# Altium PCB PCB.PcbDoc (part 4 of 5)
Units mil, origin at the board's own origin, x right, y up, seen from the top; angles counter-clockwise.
Board outline 8070.87 x 4448.94 mil, 4 copper layers (Top Layer, Layer 1, Layer 2, Bottom Layer), stack 23.756 mil thick; 263 components, 330 nets, 1677 pads, 1186 vias.
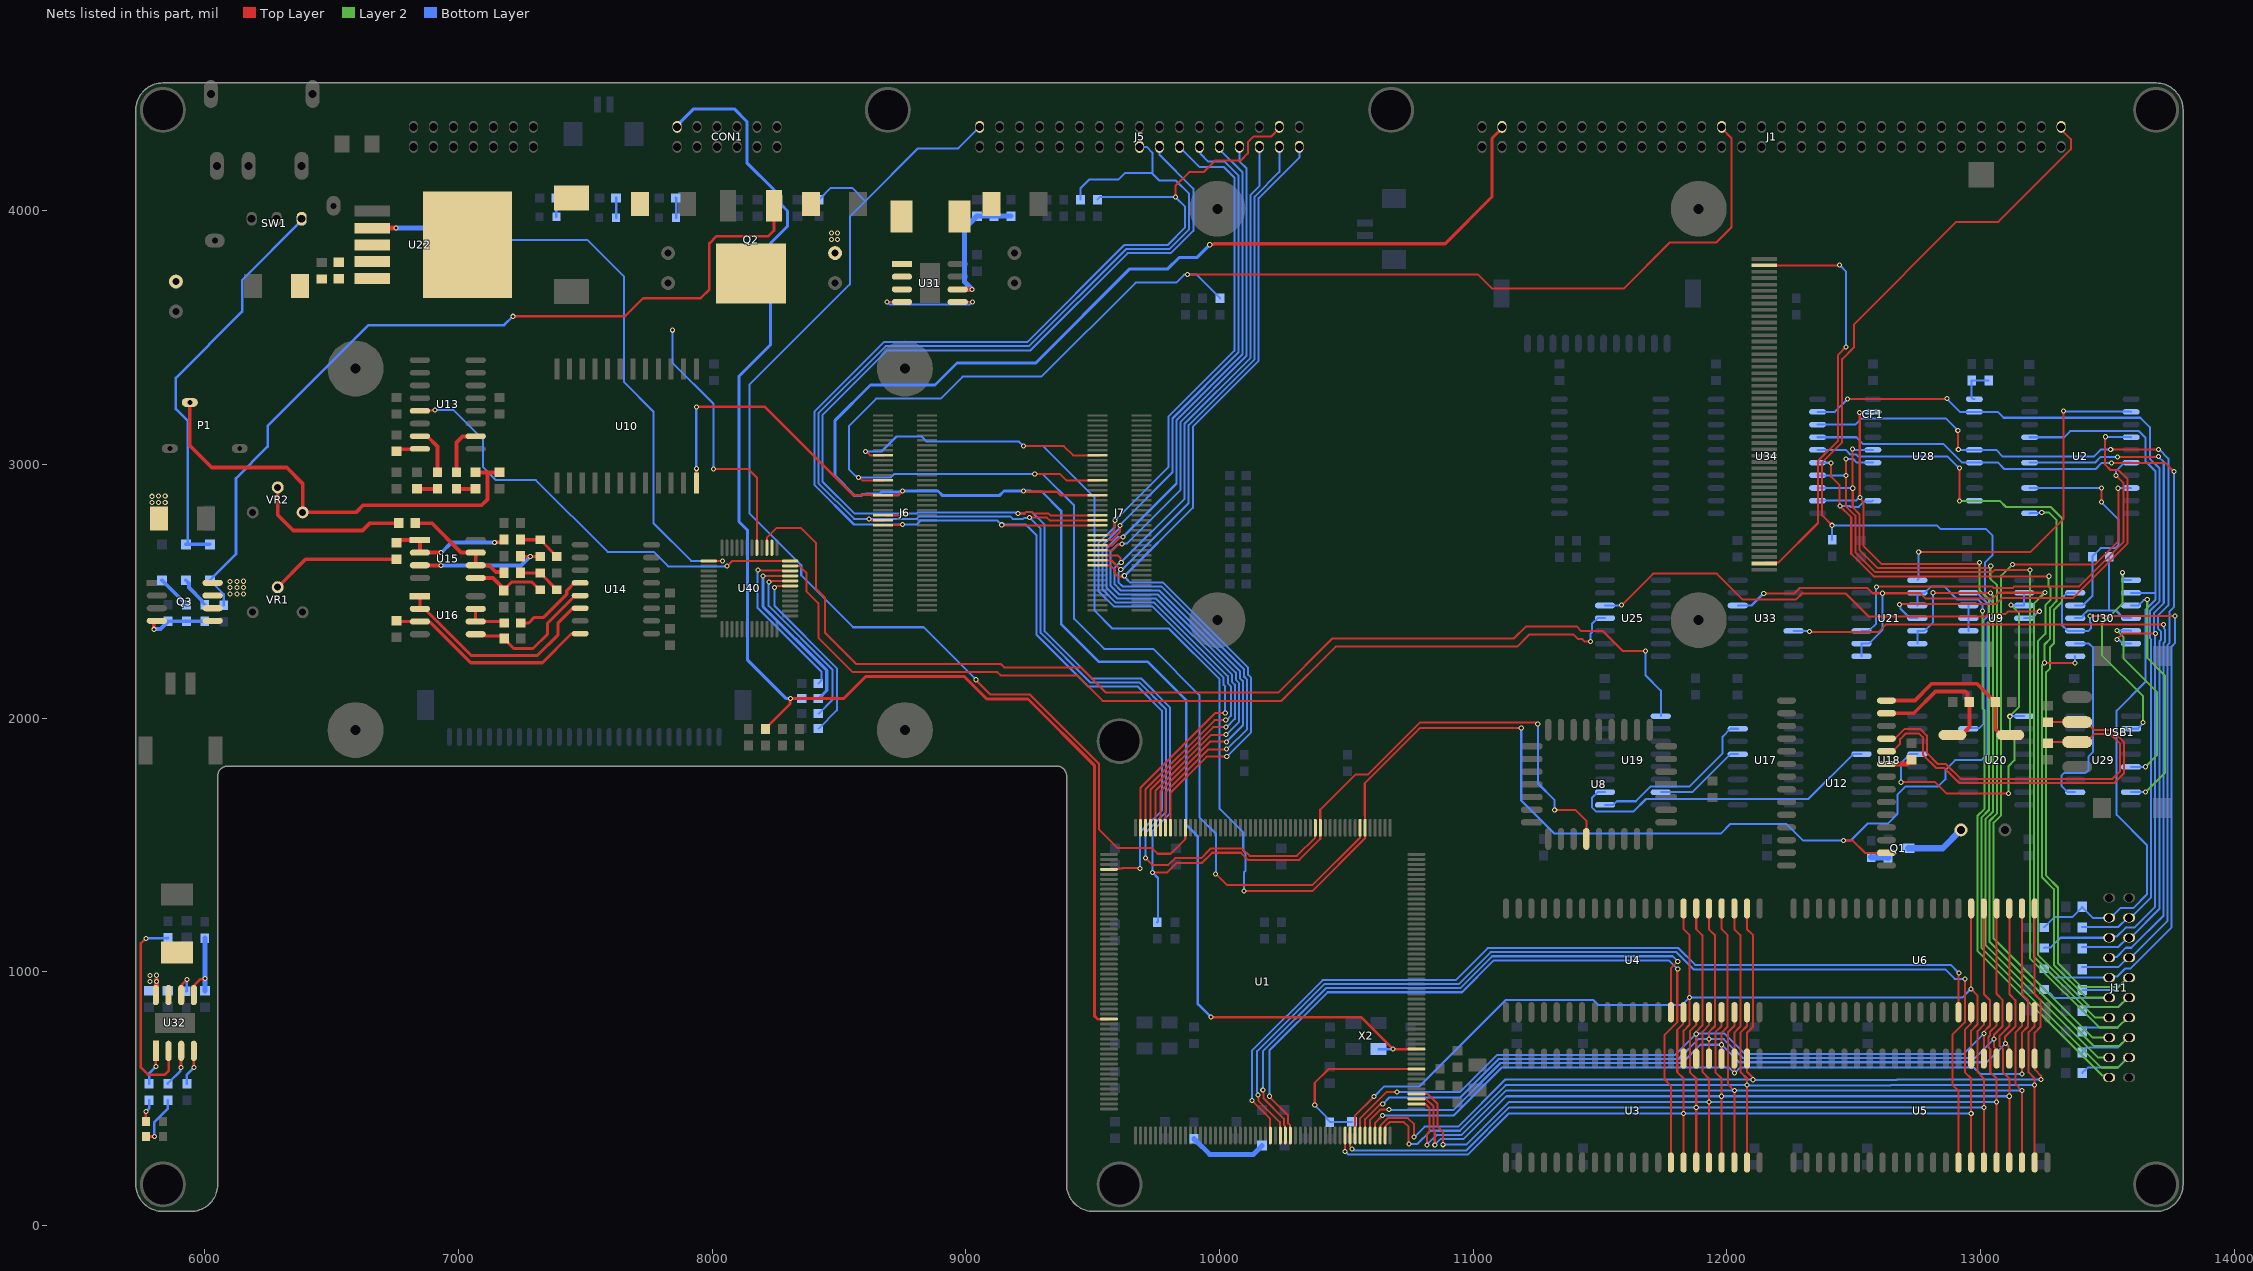
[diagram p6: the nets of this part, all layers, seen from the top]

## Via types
v1: diameter 20, hole 12, Top Layer to Bottom Layer, tented both sides, 1165 vias
v2: diameter 19.68, hole 11.81, Top Layer to Bottom Layer, tented both sides, 10 vias
v3: diameter 27.56, hole 27.56, Top Layer to Bottom Layer, 4 vias
v4: diameter 35.43, hole 35.43, Top Layer to Bottom Layer, 2 vias
v5: diameter 55.12, hole 55.12, Top Layer to Bottom Layer, 2 vias
v6: diameter 66.93, hole 66.93, Top Layer to Bottom Layer, 2 vias
v7: diameter 78.74, hole 78.74, Top Layer to Bottom Layer, 1 vias

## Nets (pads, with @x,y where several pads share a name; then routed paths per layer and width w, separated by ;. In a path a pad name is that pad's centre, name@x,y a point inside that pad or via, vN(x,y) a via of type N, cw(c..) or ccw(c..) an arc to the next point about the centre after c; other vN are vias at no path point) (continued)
LA17: J5.21 J7.32 U1.207 | length 3616.9
  Top Layer w8: J7.32@9527.56,2720.47 9528.48,2721.39 9570.06,2721.39 9586,2737.34 9586,2776.58 v1(9587.7,2778.28) ; U1.207@9688.98,1567.56 9688.98,1725.72 9983.25,2020 v1(10023,2020)
  Bottom Layer w8: J5.21@9842.52,4251.97 9922.49,4172 10018,4172 10059,4131 10059,3447.76 9799,3187.76 9799,3141 9799,2989.59 v1(9587.7,2778.28) 9586.37,2776.96 9586.37,2752 9523,2688.63 9523,2500.86 9584.86,2439 9736.88,2439 10017,2158.88 10017,2130.56 10023,2124.56 v1(10023,2020)
LA18: J5.23 J7.30 U1.206 | length 3592.4
  Top Layer w8: J7.30@9527.56,2700.79 9528.48,2701.71 9574.45,2701.71 9608.37,2735.63 v1(9608.37,2759) ; U1.206@9708.66,1567.56 9708.66,1719.66 9981,1992 v1(10025,1992)
  Bottom Layer w8: J5.23@9921.26,4251.97 9925.61,4247.62 9925.61,4224.39 9956,4194 10020.63,4194 10075,4139.63 10075,3441.14 9815,3181.14 9815,2968.87 9608.37,2762.25 v1(9608.37,2759) 9608,2759 9606.08,2757.08 9606.08,2749.08 9539,2682 9539,2507.49 9591.49,2455 9743.51,2455 10033,2165.51 10033,2137.19 10045,2125.19 10045,2008.77 10028.23,1992 v1(10025,1992)
LA19: J5.25 J7.28 U1.205 | length 3529.8
  Top Layer w8: J7.28@9527.56,2681.1 9576.48,2681.1 9607.02,2711.65 9617.76,2711.65 v1(9620.06,2713.94) ; U1.205@9728.35,1567.56 9728.35,1716.72 9975.63,1964 v1(10026,1964)
  Bottom Layer w8: J5.25@10000,4251.97 10000,4243 10091,4152 10091,3434.51 9831,3174.51 9831,2924.89 v1(9620.06,2713.94) 9619.17,2713.06 9598.06,2713.06 9555,2670 9555,2514.12 9598.12,2471 9750.14,2471 10049,2172.14 10049,2143.82 10061,2131.82 10061,1996.89 10028.11,1964 v1(10026,1964)
LA20: J5.27 J7.26 U1.204 | length 3502.9
  Top Layer w8: J7.26@9527.56,2661.42 9579.42,2661.42 9601.94,2683.94 9613.93,2683.94 v1(9615.96,2685.98) ; U1.204@9748.03,1567.56 9748.03,1713.78 9968.25,1934 10024.69,1934 v1(10025.4,1934.72)
  Bottom Layer w8: v1(9615.96,2685.98) 9613.67,2683.68 9597.68,2683.68 9571,2657 9571,2520.75 9604.75,2487 9756.76,2487 10065,2178.76 10065,2150.44 10077,2138.44 10077,1983.89 10027.83,1934.72 v1(10025.4,1934.72) ; v1@9618.3,2687.3 9634.92,2687.3 9847,2899.37 9847,3167.88 10107,3427.88 10107,4167 10078.74,4195.26 J5.27@10078.74,4251.97
LA21: J5.29 J7.24 U1.203 | length 3501.7
  Top Layer w8: J7.24@9527.56,2641.73 9599.27,2641.73 9610.7,2630.3 9610.7,2616.3 v1(9613,2614) ; U1.203@9767.72,1567.56 9767.72,1710.83 9964.88,1908 10026.2,1908 v1(10028,1906.2)
  Bottom Layer w8: v1(10028,1906.2) 10093,1971.2 10093,2145.07 10081,2157.07 10081,2185.39 9763.39,2503 9611.37,2503 9587,2527.37 9587,2593.02 9601.93,2607.95 9603.71,2607.95 9609.75,2614 v1(9613,2614) 9613,2615.11 9863,2865.11 9863,3161.25 10123,3421.25 10123,4062.63 10157.48,4097.11 J5.29@10157.48,4251.97
LA22: J5.31 J7.22 U1.202 | length 3520.6
  Top Layer w8: J7.22@9527.56,2622.05 9528.48,2621.13 9574.76,2621.13 9609.93,2585.95 v1(9611.05,2585.95) ; U1.202@9787.4,1567.56 9787.4,1707.89 9955.51,1876 10025.79,1876 v1(10027.99,1878.2)
  Bottom Layer w8: v1(9611.05,2585.95) 9611.05,2582.71 9603,2574.66 9603,2534 9618,2519 9770.02,2519 10097,2192.02 10097,2163.7 10109,2151.7 10109,1956.09 10031.11,1878.2 v1(10027.99,1878.2) ; v1@9614.76,2583.76 9879,2848 9879,3154.63 10139,3414.63 10139,4056 10236.22,4153.22 J5.31@10236.22,4251.97
LA23: J5.33 J7.20 U1.201 | length 3559
  Top Layer w8: J7.20@9527.56,2602.36 9528.48,2601.44 9570.06,2601.44 9587.47,2584.03 9587.47,2570.53 9599.3,2558.7 9622.7,2558.7 v1(9625,2561) ; U1.201@9807.09,1567.56 9807.09,1704.95 9950.16,1848.02 v1(10028.92,1848.02)
  Bottom Layer w8: v1@9624,2558 9895,2829 9895,3148 10155,3408 10155,4049.37 10314.96,4209.33 J5.33@10314.96,4251.97 ; v1(9625,2561) 9625,2557.75 9635.6,2547.15 9635.6,2546.15 9646.75,2535 9776.65,2535 10113,2198.65 10113,2170.33 10125,2158.33 10125,1944.1 v1(10028.92,1848.02)
LTP_ACK#: J11.13 U21.8 U21.9 U33.12 | length 3417
  Top Layer w8: v1(12146,2491) 12267,2491 12289,2513 12554,2513 12575,2492 v1(12615,2492) 12763,2492 12784,2471 13049.11,2471 13072.11,2494 13254,2494 v1(13255,2495)
  Layer 2 w8: v1(13255,2495) 13211,2451 13211,1060.12 13452.22,818.9 J11.13@13507.87,818.9
  Bottom Layer w8: U33.12@12043.78,2443.7 12097.7,2443.7 12145,2491 v1(12146,2491) ; U21.8@12531.5,2243.7 U21.9@12531.5,2293.7 12560.5,2293.7 12615,2348.2 v1(12615,2492)
LTP_ATUOFD#: J11.5 R102.1 U2.15 U30.6 | length 3049.6
  Top Layer w8: v1(13538,2310) 13561,2333 v1(13690,2333) ; v1(13540.16,3028.54) 13696.29,3028.54 13698.75,3031 v1(13702,3031)
  Bottom Layer w8: U2.15@13194.49,3007.09 13452.09,3007.09 13474.94,3029.94 13538.76,3029.94 v1(13540.16,3028.54) ; R102.1@13251.97,1093.27 13254.98,1096.28 13278.28,1096.28 13315.86,1133.86 J11.5@13507.87,1133.86 13512.69,1138.67 13537.67,1138.67 13572.55,1173.55 13606.55,1173.55 13689,1256 v1@13689,2333 ; v1(13538,2310) 13540.3,2307.7 13547.22,2307.7 13561.23,2293.7 U30.6@13594.02,2293.7 ; v1(13690,2333) 13690,2336.25 13684,2342.25 13684,2414 13723,2453 13723,3010 v1(13702,3031)
LTP_BUSY: J11.15 U2.8 | length 2839.7
  Top Layer w8: v1(13126,2605) 13451.75,2605 13544,2697.25 13544,2905 v1(13543,2906)
  Layer 2 w8: v1(13126,2605) 13082,2561 13082,1617.49 13052,1587.49 13052,1131 13442.84,740.16 J11.15@13507.87,740.16
  Bottom Layer w8: v1(13543,2906) 13543.55,2906.55 13593.94,2906.55 U2.8@13594.49,2907.09
LTP_D0: C115.1 J11.4 U28.2 U34.2 | length 3585.9
  Top Layer w8: v1(12477,3258) 12477.5,3258.5 12867.5,3258.5 v1(12868,3259)
  Bottom Layer w8: U34.2@12358.27,3207.09 12426.09,3207.09 v1(12477,3258) ; v1@12867.5,3258.5 12918.91,3207.09 U28.2@12976.38,3207.09 13068.91,3207.09 13092,3184 13631,3184 13668,3147 13668,3023 13707,2984 13707,2461 13668,2422 13668,2315 13673,2310 13673,1474 13673,1293.08 13592.52,1212.6 J11.4@13586.61,1212.6 13580.71,1212.6 13544.78,1176.67 C115.1@13401.57,1176.67
LTP_D1: C114.1 J11.6 U28.5 U34.3 | length 3690.6
  Top Layer w8: v1(12911,3134) 12912,3133 12912,3059 v1(12913,3058) ; v1(13514,3058) 13701,3058 v1(13702,3059)
  Bottom Layer w8: U34.3@12358.27,3157.09 12507.09,3157.09 12530.09,3180.09 12864.91,3180.09 v1(12911,3134) ; v1(12913,3058) 12913.45,3057.55 12975.93,3057.55 U28.5@12976.38,3057.09 13062.91,3057.09 13089,3031 13447,3031 13474,3058 v1(13514,3058) ; C114.1@13401.57,1097.44 13544.29,1097.44 13580.71,1133.86 J11.6@13586.61,1133.86 13592.52,1133.86 13706,1247.34 13706,2301.88 13712,2307.88 13712,2342.11 13700,2354.11 13700,2403 13741,2444 13741,3023.11 13705.11,3059 v1(13702,3059)
LTP_D2: C113.1 J11.8 U28.6 U34.4 | length 3674.3
  Top Layer w8: v1(13517,3006) 13729,3006 v1(13763,2972)
  Bottom Layer w8: U34.4@12358.27,3107.09 12510.91,3107.09 12537.91,3080.09 12854.91,3080.09 12927.91,3007.09 U28.6@12976.38,3007.09 13069.91,3007.09 13095,2982 13455,2982 13479,3006 v1(13517,3006) ; C113.1@13401.57,1018.21 13543.8,1018.21 13580.71,1055.12 J11.8@13586.61,1055.12 13592.52,1055.12 13738,1200.6 13738,2288.63 13745,2295.63 13745,2419 13763,2437 v1(13763,2972)
LTP_D3: C112.1 J11.10 U28.9 U34.5 | length 3548.7
  Top Layer w8: v1(12917,2985) 12917.5,2984.5 12917.5,2856.5 v1(12918,2856)
  Layer 2 w8: v1(12918,2856) 13077,2856 13101,2832 13277,2832 13322,2787 13322,2459 13291,2428 13291,2296 13275,2280 13275,2197 13259,2181 13259,1379 13306,1332 13306,1033 13400.02,938.98 13543.31,938.98 13580.71,976.38 J11.10@13586.61,976.38
  Bottom Layer w8: U34.5@12358.27,3057.09 12468.79,3057.09 12486.89,3039 12510,3039 12517,3032 12870,3032 v1(12917,2985) ; v1(12918,2856) 12918.55,2856.55 12975.83,2856.55 U28.9@12976.38,2857.09 ; C112.1@13402,927.95 13532.28,927.95 13580.71,976.38 J11.10@13586.61,976.38
LTP_D4: C111.1 J11.12 U28.12 U34.6 | length 3587.3
  Top Layer w8: v1(12412,3006) 12412,2951 12444,2919 v1@12444,2833 ; v1(12446.61,2835.61) 12491,2791.23 12491,2647 12579,2559 v1(13270,2559)
  Layer 2 w8: v1(13270,2559) 13269,2558 13269,2518.56 13277,2510.56 13277,2466 13256,2445 13256,2332 13227,2303 13227,1066.75 13433.75,860 13543.07,860 13580.71,897.64 J11.12@13586.61,897.64
  Bottom Layer w8: U34.6@12358.27,3007.09 12358.82,3006.55 12411.45,3006.55 v1(12412,3006) ; v1(12446.61,2835.61) 12485.27,2835.61 12487.88,2833 12521,2833 12542.42,2854.42 12573.7,2854.42 U28.12@12576.38,2857.09 ; C111.1@13402,845.96 13416.04,860 13542.77,860 13580.41,897.64 J11.12@13586.61,897.64
LTP_D5: C110.1 J11.14 U28.15 U34.7 | length 3589.8
  Top Layer w8: v1(12471,3022) v1(12471,2957) 12471,2833.85 12507,2797.85 12507,2653.63 12585.63,2575 13047.11,2575 13055.11,2583 v1(13195,2583)
  Layer 2 w8: v1(13195,2583) 13195,1053.49 13467.98,780.51 13542.32,780.51 13580.71,818.9 J11.14@13586.61,818.9
  Bottom Layer w8: U34.7@12358.27,2957.09 12358.32,2957.05 v1(12471,2957) v1(12471,2957) ; v1(12471,3022) 12498,3022 12512.91,3007.09 U28.15@12576.38,3007.09 ; C110.1@13402,763.98 13402,765.47 13416.5,779.98 13418,779.98 13418.54,780.51 13542.32,780.51 13580.71,818.9 J11.14@13586.61,818.9
LTP_D6: C109.1 J11.16 U28.16 U34.8 | length 3631.2
  Top Layer w8: v1(12496,3061) 12496.5,3060.5 12496.5,2906.5 v1(12497,2906) 12497,2830.48 12523,2804.48 12523,2664 12596,2591 13030.31,2591 13039.31,2600 v1(13041,2600)
  Layer 2 w8: v1(13041,2600) 13039,2598 13039,2550 13066,2523 13066,1624.12 13036,1594.12 13036,1118 13446,708 13548.55,708 13580.71,740.16 J11.16@13586.61,740.16
  Bottom Layer w8: U34.8@12358.27,2907.09 12358.82,2906.55 12496.45,2906.55 v1(12497,2906) ; v1(12496,3061) 12499.25,3061 12503.2,3057.05 12576.33,3057.05 U28.16@12576.38,3057.09 ; C109.1@13402,681.99 13402,683.48 13416.5,697.99 13418,697.99 13422.01,702 13542.55,702 13580.71,740.16 J11.16@13586.61,740.16
LTP_D7: C108.1 J11.18 U28.19 U34.9 | length 3797.8
  Top Layer w8: v1(12524,3205) 12524.5,3204.5 12524.5,2869.5 v1(12525,2869) 12525,2865.89 12539,2851.89 12539,2680 12612,2607 12986.75,2607 12992.75,2613 v1(12996,2613)
  Layer 2 w8: v1(12996,2613) 12996,2504.89 13034,2466.89 13034,1637.37 13004,1607.37 13004,1095 13476.95,622.05 13541.34,622.05 13580.71,661.42 J11.18@13586.61,661.42
  Bottom Layer w8: U34.9@12358.27,2857.09 12359.21,2858.03 12510.79,2858.03 12521.75,2869 v1(12525,2869) ; v1(12524,3205) 12525.05,3206.05 12575.33,3206.05 U28.19@12576.38,3207.09 ; C108.1@13402,600 13402,601.5 13416.5,616 13418,616 13424,622 13541.29,622 13580.71,661.42 J11.18@13586.61,661.42
LTP_ERROR#: J11.7 U33.5 | length 2906.7
  Top Layer w8: v1(12326,2342) 12328,2340 12599,2340 12627,2368 13171.23,2368 13172.23,2369 v1(13722,2369)
  Bottom Layer w8: U33.5@12263.78,2342.52 v1@12326,2342.52 ; J11.7@13507.87,1055.12 13510.72,1057.96 13536.96,1057.96 13573.49,1094.49 13595.18,1094.49 13722,1221.31 13722,2295.25 13728,2301.25 13728,2348.74 13724.3,2352.44 13724.3,2366.7 v1(13722,2369)
LTP_INIT#: J11.9 R105.1 U30.10 U30.13 | length 2511.2
  Top Layer w8: v1(13432.11,2402) 13432.61,2402.5 13766.5,2402.5 v1(13767,2403)
  Bottom Layer w8: R105.1@13253.47,1011.55 13266.97,998.05 13272.48,998.05 13294.15,976.38 J11.9@13507.87,976.38 13512.69,981.19 13539.19,981.19 13570.22,1012.22 13591.65,1012.22 13754,1174.57 13754,2282 13767,2295 v1(13767,2403) ; U30.13@13374.02,2493.7 13342.7,2493.7 13322,2473 13322,2366.72 13345.02,2343.7 U30.10@13374.02,2343.7 13426.7,2343.7 13436,2353 13436,2373.93 13432.11,2377.82 v1(13432.11,2402)
LTP_PE: J11.17 U21.5 U21.6 | length 2546.3
  Top Layer w8: v1(12814,2494) 12814.5,2493.5 13040.5,2493.5 v1(13040.68,2493.68)
  Layer 2 w8: v1(13040.68,2493.68) 13040.68,2490.43 13050,2481.1 13050,1630.75 13020,1600.75 13020,1106 13464.58,661.42 J11.17@13507.87,661.42
  Bottom Layer w8: U21.6@12751.5,2293.7 U21.5@12751.5,2343.7 12780.5,2343.7 12814,2377.2 v1(12814,2494) v1@12813.85,2493.85
LTP_SEL: J11.19 U21.2 U21.3 | length 2455.6
  Layer 2 w8: v1(13009,2422) 13009,2038.38 13017,2030.38 13017,1643 12988,1614 12988,1083 13479.63,591.37 13485.86,591.37 13494.55,582.68 J11.19@13507.87,582.68
  Bottom Layer w8: U21.3@12751.35,2443.85 U21.3@12751.5,2443.7 U21.2@12751.5,2493.7 12780.5,2493.7 12805.8,2519 12857,2519 12908,2468 12989.98,2468 13009,2448.98 v1(13009,2422)
LTP_SELIN#: J11.11 R104.1 U2.11 U30.8 | length 2605.8
  Top Layer w8: v1(13253,2218) 13253.5,2217.5 13372.5,2217.5 v1(13373,2217)
  Layer 2 w8: v1(13242,2810) 13271,2810 13300,2781 13300,2460 13275,2435 13275,2312 13253,2290 13253,2217.31 13243,2207.31 13243,1372.37 13290,1325.37 13290,1026.37 13418.73,897.64 J11.11@13507.87,897.64
  Bottom Layer w8: U2.11@13194.49,2807.09 13195.94,2808.55 13240.55,2808.55 v1(13242,2810) ; R104.1@13251.97,929.82 13265.47,916.32 13273.68,916.32 13294,896 13313.48,896 13313.53,895.95 13425.47,895.95 13425.52,896 13506.24,896 J11.11@13507.87,897.64 ; v1(13373,2217) 13373,2242.69 U30.8@13374.02,2243.7
LTP_STROBE#: C116.1 J11.3 R106.1 U2.17 U30.2 | length 2997.2
  Bottom Layer w8: U2.17@13194.49,3107.09 13330.09,3107.09 13354,3131 13625.57,3131 13651,3105.57 13651,3012 13691,2972 13691,2493.38 ; R106.1@13251.97,1177.17 13253.47,1177.17 13291.3,1215 13362.17,1215 C116.1@13401.57,1254.41 ; C116.1@13401.57,1255.9 C116.1@13401.57,1254.41 ; U30.2@13594.02,2493.7 13595.14,2492.58 13691,2492.58 13691,2467.63 ; 13690.43,2467.06 13651,2427.63 13651,2143 13537,2029 13537,1618 13657,1498 13657,1305.61 13602.39,1251 13552.18,1251 13513.78,1212.6 J11.3@13507.87,1212.6 13443.39,1212.6 C116.1@13401.57,1254.41
LTPIO: U40.2
LTPSW: U25.11 U40.47 | length 3751.8
  Top Layer w8: U40.47@8307.43,2599.58 8308.16,2598.85 8346.15,2598.85 8372,2573 8372,2500.26 8419,2453.26 8419,2317.12 8555.12,2181 9125,2181 9138,2168 9439.75,2168 9539.75,2068 10244.75,2068 10458.44,2281.7 11174.41,2281.7 11222.41,2329.7 11395.42,2329.7 11414.12,2311 11431,2311 11441,2301 v1(11463,2301)
  Bottom Layer w8: v1(11463,2301) 11463,2333 11468.16,2338.16 11468.16,2370.7 11491.16,2393.7 U25.11@11520.16,2393.7
MA0: U1.108 U3.17 U4.17 U5.17 U6.17 | length 3751.7
  Top Layer w8: U1.108@10776.77,518.03 10820.97,518.03 10860,479 10860,390 10881.06,368.94 v1(10881.06,317.94) ; U3.17@11930,248 v1(11930,486) 11930,579 11905,604 11905,764 11930,789 U4.17@11930,840 ; U5.17@13064,248 v1(13064,486) 13064,579 13039,604 13039,694.39 13032.34,701.05 13032.34,744.6 13038,750.27 13038,763 13064,789 U6.17@13064,840
  Bottom Layer w8: v1(10881.06,317.94) 10972.81,317.94 11140.86,486 v1(11930,486) v1@13063,486
MA1: U1.107 U3.18 U4.18 U5.18 U6.18 | length 3813
  Top Layer w8: U1.107@10776.77,498.35 10777.5,497.62 10815.61,497.62 10844,469.23 10844,374 10849,369 10849,317.11 v1(10849.11,317) ; U3.18@11980,248 v1(11980,509) 11980,579 11955,604 11955,761 11980,786 U4.18@11980,840 ; U5.18@13114,248 v1(13114,509) 13114,579 13089,604 13089,694.39 13076.34,707.05 13076.34,748.34 13114,786 U6.18@13114,840
  Bottom Layer w8: v1(10849.11,317) 10849.11,317.11 10873,341 10963,341 11131,509 v1(11980,509) v1@13113,509
MA2: U1.106 U3.19 U4.19 U5.19 U6.19 | length 3867.7
  Top Layer w8: U1.106@10776.77,478.66 10777.5,477.93 10812.67,477.93 10828,462.6 10828,370 10818,360 v1(10818,317) ; U3.19@12030,248 v1(12030,531) 12005,556 12005,761 12030,786 U4.19@12030,840 ; U5.19@13164,248 v1(13164,531) 13139,556 13139,761 13164,786 U6.19@13164,840
  Bottom Layer w8: v1(10818,317) 10858,357 10955,357 11129,531 v1(12030,531) v1(13164,531)
MA3: U1.103 U3.20 U4.20 U5.20 U6.20 | length 3998.3
  Top Layer w8: U1.103@10653.54,354.33 10654.27,355.06 10654.27,390.53 10670.74,407 10727,407 10746,388 10746,323 v1(10748,321) ; U3.20@12080,248 v1(12080,553) 12080,579 12055,604 12055,761 12080,786 U4.20@12080,840 ; U5.20@13214,248 v1(13214,553) 13214,579 13190,603 13190,762 13214,786 U6.20@13214,840
  Bottom Layer w8: v1(10748,321) 10781,321 10833,373 10948.37,373 11128.37,553 v1(12080,553) 12081,552 12646.5,552 12647.5,553 v1(13214,553)
MA4: U1.102 U3.23 U4.23 U5.23 U6.23 | length 4221.2
  Top Layer w8: U1.102@10633.86,354.33 10634.59,355.06 10634.59,393.47 10664.11,423 10742.91,423 10768,397.91 v1(10768,348) ; U4.23@12080,1249.45 12080,1168 12104,1144 12104,784 12080,760 U3.23@12080,657.45 12080,605.45 12101.7,583.74 12101.7,576.3 v1(12104,574) ; U6.23@13214,1249.45 13214,912 13238,888 13238,784 13214,760 U5.23@13214,657.45 13215.75,655.7 13215.75,613.25 13238.94,590.06 13238.94,575.06 v1(13239,575)
  Bottom Layer w8: v1(10768,348) 10809,389 10941.75,389 11127.75,575 12103,575 v1(12104,574) 12671,574 12672,575 v1(13239,575)
MA5: U1.101 U3.24 U4.24 U5.24 U6.24 | length 4064.7
  Top Layer w8: U1.101@10614.9,353.6 U1.101@10614.17,354.33 10614.17,404.17 v1(10643,433) ; U4.24@12030,1249.45 12030,1168 12054,1144 12054,784 12030,760 U3.24@12030,657.45 12030.5,656.95 12030.5,600.5 v1(12031,600) ; U6.24@13164,1249.45 13164,912 13188,888 13188,784 13164,760 U5.24@13164,657.45 13164.5,656.95 13164.5,597.5 v1(13165,597)
  Bottom Layer w8: v1(10643,433) 10924,433 11114,623 12008,623 v1(12031,600) 12054,623 12973,623 12999,597 v1(13165,597)
MA6: U1.100 U3.25 U4.25 U5.25 U6.25 | length 3984
  Top Layer w8: U1.100@10594.49,354.33 10594.49,415.6 10634.89,456 v1(10669,456) ; U3.25@11980,657.45 v1(11980,712) 11980,760 12004,784 12004,1144 11980,1168 U4.25@11980,1249.45 ; v1@13096.71,717.96 13096.71,742.71 13138,784 13138,888 13114,912 U6.25@13114,1249.45 ; v1@13099.32,717.32 13111,705.65 13111,660.45 U5.25@13114,657.45
  Bottom Layer w8: v1(10669,456) 10670,455 10923.37,455 11108.37,640 11824,640 11896,712 v1(11980,712) 12049,643 13025,643 v1(13098.34,716.34)
MA7: U1.99 U3.26 U4.26 U5.26 U6.26 | length 3969.5
  Top Layer w8: U1.99@10574.8,354.33 10574.8,418.54 10631.96,475.7 10641.7,475.7 v1(10644,478) ; U3.26@11930,657.45 11930.44,657.89 11930.44,733.56 v1(11930.89,734) ; v1@11930,734 11930,762 11954,786 11954,1144 11930,1168 U4.26@11930,1249.45 ; U5.26@13064,657.45 13060.94,660.51 13060.94,696.03 13054.34,702.64 v1(13054.34,735.53) 13054.34,752.34 13088,786 13088,888 13064,912 U6.26@13064,1249.45
  Bottom Layer w8: v1(10644,478) 10670,504 10949.75,504 11101.75,656 11810,656 11888.22,734.22 11930.89,734.22 11988.9,734.22 12064.11,659 12977.8,659 v1(13054.34,735.53)
MA8: U1.98 U3.27 U4.27 U5.27 U6.27 | length 3955.6
  Top Layer w8: U1.98@10555.12,354.33 10555.12,421.49 10659.63,526 v1(10700,526) ; U3.27@11880,657.45 v1(11880,755) 11880,764 11904,788 11904,1144 11880,1168 U4.27@11880,1249.45 ; v1(13013.65,756.22) 13014,755.87 U5.27@13014,657.45 ; v1@13014,756 13014,764 13038,788 13038,888 13014,912 U6.27@13014,1249.45
  Bottom Layer w8: v1(10700,526) 10949.12,526 11095.12,672 11797,672 v1(11880,755) 11881,756 11992,756 12073,675 12932.43,675 v1(13013.65,756.22)
MA9: U1.97 U3.28 U4.28 U5.28 U6.28 | length 3954.3
  Top Layer w8: U1.97@10535.43,354.33 10535.43,433.43 v1(10610,508) ; U3.28@11830,657.45 11830,768 11854,792 v1(11854,899) 11854,1144 11830,1168 U4.28@11830,1249.45 ; U5.28@12964,657.45 12964,768 12988,792 12988,907 v1(12963,932) 12963.5,932.5 12963.5,1248.95 U6.28@12964,1249.45
  Bottom Layer w8: v1(10610,508) 10650,548 10789,548 11130,889 11473,889 11493,869 11824,869 v1(11854,899) 12930,899 v1(12963,932)
MA10: U1.96 U3.16 U4.16 U5.16 U6.16 | length 3845.8
  Top Layer w8: U1.96@10515.75,354.33 10515.75,310.5 10522,304.25 v1(10522,301) ; U3.16@11880,248 v1(11880,464) 11880,579 11855,604 11855,766 11880,791 U4.16@11880,840 ; U5.16@13014,248 13014,579 12989,604 12989,766 13014,791 U6.16@13014,840
  Bottom Layer w8: v1(10522,301) 10525.25,301 10531.25,295 10972.49,295 11141.49,464 v1(11880,464) v1(13014,464)
MA11: U1.95 U3.15 U4.15 U5.15 U6.15 | length 3830.5
  Top Layer w8: v1(10495.04,290.45) 10495.55,290.96 10495.55,353.82 U1.95@10496.06,354.33 ; U3.15@11830,248 v1(11830,441) 11830,579 11805,604 11805,771 11828.53,794.53 11828.53,838.53 U4.15@11830,840 ; U5.15@12964,248 v1(12964,441) 12964,579 12939,604 12939,772 12962.53,795.53 12962.53,838.53 U6.15@12964,840
  Bottom Layer w8: v1(10495.04,290.45) 10497.55,290.45 10509,279 10979.12,279 11141.12,441 v1(11830,441) v1(12964,441)
MASTER#: J5.2 R57.1 U1.198 | length 4737.1
  Top Layer w8: v1(9041,2151) 9041,2148 9096,2093 9253,2093 9525,1821 9525,1562 9600,1487 9735,1487 9757,1465 9808.11,1465 9865.41,1522.3 9865.41,1566.83 U1.198@9866.14,1567.56
  Bottom Layer w8: R57.1@8422,4043 8422,4044.5 8467.5,4090 8552,4090 8603.96,4038.04 ; v1(9041,2151) 8834,2358 8555.89,2358 8351.44,2562.44 8351.44,2602.93 8147,2807.37 8147,3313.63 8543,3709.63 8543,3977.09 8603.96,4038.04 ; J5.2@9055.12,4330.71 8970.41,4246 8811.91,4246 8603.96,4038.04
MCS16#: J5.32 J6.36 J7.36 R55.1 U1.4 | length 6300.1
  Top Layer w8: J6.36@8681.1,2759.84 8682.02,2760.76 8748.76,2760.76 v1(8751,2763) ; v1(9142,2762) 9144.16,2759.84 J7.36@9527.56,2759.84 ; U1.4@9564.65,1403.86 9565.37,1404.59 9602.68,1404.59 9605.64,1407.54 9617.54,1407.54 9618,1408 9686,1408 v1(9687,1407) ; v1(9827,4054) 9827,4099 9880.35,4152.35 9937.45,4152.35 9983.1,4198 10084,4198 10112,4226 10112,4270 10134,4292 10203.42,4292 10236.22,4324.8 J5.32@10236.22,4330.71
  Bottom Layer w8: v1(8751,2763) 8559.41,2763 8403,2919.41 8403,3207.59 8677.41,3482 9242.12,3482 9625.12,3865 9795.75,3865 9865,3934.25 9865,4016 v1(9827,4054) 9529,4054 R55.1@9519,4044 ; v1@8751.07,2763 8807.37,2763 8823.37,2779 9125,2779 v1(9142,2762) 9143.1,2763.1 9235.9,2763.1 9279,2720 9279,2328.88 9483.37,2124.51 9677.66,2124.51 9773,2029.17 9773,1635.37 9687,1549.37 v1(9687,1407)
MCU_ADC1: C23.1 L4.2 Q3.5 Q3.6 Q3.7 Q3.8 U31.3 U31.4 U31.5 U40.5 | length 1539.5
  Top Layer w8: v1(8006,2982) 8143,2982 8176.53,2948.47 U40.5@8176.53,2671.43 ; v1(8690,3640) 8690.08,3640.08 8748.43,3640.08 U31.4@8748.5,3640.16 ; U31.5@8968.5,3640.16 8968.93,3640.58 9026.58,3640.58 v1(9027,3641)
  Bottom Layer w8: v1(7844,3529) 7844,3498.11 7843,3497.11 7843,3401 8006,3238 v1(8006,2982) ; v1(8690,3640) 8690.69,3640 8700.69,3630 9016,3630 v1(9027,3641)
  other v1: 6100,2489.11 6126.39,2489.37 6152.78,2489.63 6100,2514 6126.39,2514.26 6152.78,2514.51 6100,2538.89 6126.39,2539.14 6152.78,2539.4 8470.23,3886 8495.11,3886 8469.97,3912.39 8494.86,3912.39
MEMR#: J5.19 J6.40 J7.40 R63.1 U1.171 U8.24 | length 8128.4
  Top Layer w8: J6.40@8681.1,2799.21 8739.83,2799.21 8747.75,2807.13 v1(8751,2807.13) ; v1(9206,2807.13) 9232.75,2807.13 9237.61,2812 9262.09,2812 9266.89,2807.2 9325.8,2807.2 9333.79,2799.21 J7.40@9527.56,2799.21 ; v1(9736,1391.51) 9794.88,1391.51 9832.37,1429 9931.44,1429 9971.44,1469 10084.24,1469 10112.24,1441 10314.89,1441 10397.64,1523.75 10397.64,1638.75 10536.94,1778.06 10586.17,1778.06 10791.11,1983 11245.75,1983 11251.75,1977 v1(11255,1977) ; v1(11322,1638) 11403,1638 11446.46,1594.54 U8.24@11446.46,1523.62
  Bottom Layer w8: v1(9206,2807.13) 9203.7,2809.43 9196.89,2809.43 9195.31,2811 8810.12,2811 8806.25,2807.13 8560.53,2807.13 8435,2932.67 8435,3194.33 8690.67,3450 9255.37,3450 9638.37,3833 9809,3833 9897,3921 9897,4087 9763.78,4220.22 J5.19@9763.78,4251.97 ; v1@9206.07,2807.07 9206.13,2807.13 9232.75,2807.13 9237.61,2812 9261.11,2812 9311,2762.11 9311,2342.14 9496.63,2156.51 9690.92,2156.51 9805,2042.42 9805,1622.12 9736,1553.12 v1(9736,1391.51) 9758,1369.51 9758,1198 R63.1@9755,1195 ; v1(11255,1977) 11256,1976 11256,1742 11322,1676 v1(11322,1638)
MEMW#: J5.17 J6.38 J7.38 R62.1 U1.172 | length 6583.3
  Top Layer w8: 8626.79,2779.53 J6.38@8681.1,2779.53 ; v1(9252,2790) 9320,2790 9330.47,2779.53 J7.38@9527.56,2779.53 ; v1(9709,1448) 9736,1421 9799,1421 9826,1448 9927.81,1448 9964.81,1485 10090.87,1485 10118.87,1457 10305.5,1457 10377.22,1528.72 10377.22,1566.83 U1.172@10377.95,1567.56
  Bottom Layer w8: R62.1@9452.67,4044 9452.67,4089.67 9486,4123 9602,4123 9627,4148 9734.63,4148 ; J5.17@9685.04,4251.97 9713.03,4251.97 9736,4229 9736,4147 9764,4119 9829,4119 9881,4067 9881,3927.63 9802.37,3849 9631.75,3849 9248.75,3466 8684.04,3466 8419,3200.96 8419,2926.04 8559.97,2785.07 8806.81,2785.07 8816.75,2795 9175.37,2795 9185.24,2785.13 9226,2785.13 9230,2789.13 9251.13,2789.13 v1(9252,2790) 9295,2747 9295,2335.51 9490,2140.51 9684.29,2140.51 9789,2035.8 9789,1628.75 9709,1548.75 v1(9709,1448)
  other v1: 8618,2785.07
MSCLK: C8.1 CON1.2 R15.1 R48.1 U1.34 | length 5479.1
  Top Layer w10: 9519.69,813.31 U1.34@9564.65,813.31
  Top Layer w12: R48.1@8210.67,1957 8210.67,1958.5 8307.47,2055.3 8307.47,2075.47 v1(8309,2077) 8519,2077 8605,2163 8995.06,2163 9083.06,2075 9245.54,2075 9507,1813.54 9507,826 9519.69,813.31
  Bottom Layer w12: CON1.2@7862.2,4330.71 7862.2,4336.61 7927.59,4402 8087,4402 8137,4352 8137,4189 8244.5,4081.5 8244.5,4056.48 8257,4043.98 C8.1@8258.5,4043.98 8260,4043.98 8272.5,4031.48 8272.5,4023.5 8297,3999 8297,3939 8231,3873 8231,3472.88 8105.89,3347.76 8105.89,2774.24 8139,2741.12 8139,2230 8292.5,2076.5 R15.1@8353.61,2076.5
MUTE#: U13.5 U40.48 | length 1788.7
  Top Layer w8: U13.5@6848,3211.2 6849.4,3212.6 6906.6,3212.6 v1(6908,3214) ; v1(8059.22,2598.74) 8059.22,2599.22 8079.27,2619.27 U40.48@8307.43,2619.27
  Bottom Layer w8: v1(6908,3214) 6981,3214 7097,3098 7097,2989 7148,2938 7305,2938 7588,2655 7770,2655 7827,2598 8058.48,2598 v1(8059.22,2598.74)
NetC18_1: C18.1 C19.1 C20.1 D20.K U22.5
NetC20_2: C20.2 U22.4
NetC26_1: C26.1 C27.1 D7.K U32.8 | length 62.1
  Top Layer w20: v1@5808.94,967.36 5809.45,966.85 U32.8@5809.45,905.51
  other v1: 5783.15,960.96 5809.55,961.22 5783.15,985.85 5809.55,986.1 5791.22,2849.49 5817.61,2849.74 5844,2850 5791.22,2874.37 5817.61,2874.63 5844,2874.89
NetC28_1: C28.1 R135.1 U32.5 | length 299.2
  Top Layer w10: U32.5@5957,908 5959.68,910.68 5959.68,947.87 5982.34,970.53 5998.09,970.53 v1(6000,972.44)
  Bottom Layer w20: R135.1@6000,1131.85 v1(6000,972.44) 6000,925.56 C28.1@6001,924.56
NetC43_2: C43.2 U14.16 U16.3 | length 840.5
  Top Layer w12: C43.2@6755.91,2384 6759.53,2380.38 U16.3@6848,2380.38 6850.3,2378.08 6888.63,2378.08 7048.72,2218 7331,2218 7444.09,2331.09 7478.09,2331.09 U14.16@7480,2333
NetC44_1: C44.1 U14.13 U16.5 | length 548
  Top Layer w12: U16.5@7068,2330.38 7099.25,2330.38 7105.63,2324 7170.02,2324 C44.1@7180.02,2314 7180.02,2312.5 7218.52,2274 7294,2274 7351,2331 7351,2374 7460,2483 U14.13@7480,2483
NetC45_2: C45.2 R29.2 U15.3 | length 528.5
  Top Layer w12: C45.2@7244.49,2638.13 7245.29,2637.33 v1(7283,2637.33) R29.2@7322,2637.33
  Top Layer w15: U15.3@6848,2602.38 6848.69,2601.69 6931.31,2601.69 v1(6932,2601)
  Bottom Layer w15: v1(6932,2601) 7246.67,2601 v1(7283,2637.33)
NetC46_1: C46.1 C50.1 U15.6 U15.7 | length 460.5
  Top Layer w15: C50.1@6829.24,2768.38 6894.62,2768.38 7010.62,2652.38 U15.7@7068,2652.38 U15.6@7068,2602.38 7120.62,2602.38 7147.29,2575.71 7176.68,2575.71 C46.1@7179.51,2572.88
NetC46_2: C46.2 R31.2 R32.1 | length 178.1
  Top Layer w12: C46.2@7244.49,2572.88 7245.7,2571.67 R31.2@7328,2571.67 ; R31.2@7322,2571.67 7323.5,2571.67 7335,2560.17 7335,2558.67 7374,2519.67 7374,2517.5 7384.83,2506.67 R32.1@7387,2506.67
NetC47_1: C47.1 C49.1 U15.1 U15.2 | length 499.5
  Top Layer w15: C49.1@6756.16,2691 6767.16,2702 6777.07,2702 6777.44,2702.38 U15.1@6848,2702.38 U15.2@6848,2652.38 6848.19,2652.19 6931.81,2652.19 v1(6932,2652) ; v1(7143,2692) 7143.96,2692.96 7169.09,2692.96 C47.1@7179.51,2703.38
  Bottom Layer w15: v1(6932,2652) 6972,2692 v1(7143,2692)
NetC47_2: C47.2 R28.2 R29.1 | length 182.5
  Top Layer w12: C47.2@7244.49,2703.38 7244.87,2703 R28.2@7328,2703 ; R28.2@7322,2703 7323.5,2703 7335,2691.5 7335,2690 7374,2651 7374,2648.83 7385.5,2637.33 R29.1@7391.5,2637.33
NetC48_2: C48.2 R32.2 U15.5 | length 301.8
  Top Layer w12: C48.2@7179.02,2503 7179.02,2504.5 7211.52,2537 7288,2537 7307.5,2517.5 7310.5,2517.5 R32.2@7322,2506
  Top Layer w15: U15.5@7068,2552.38 7135.99,2552.38 7179.49,2508.88 C48.2@7179.49,2507.38
NetC49_2: C49.2 VR1.W | length 514.4
  Top Layer w15: VR1.W@6287.4,2515.75 6397.67,2626.02 C49.2@6756.16,2626.02
NetC50_2: C50.2 VR2.W | length 623.4
  Top Layer w15: VR2.W@6287.4,2909.45 6287.4,2800.6 6349,2739 6622,2739 6651.38,2768.38 C50.2@6764.26,2768.38
NetC55_2: C55.2 R35.2 | length 74.8
  Top Layer w15: R35.2@6992.13,2903.5 C55.2@7066.93,2903.52
NetC56_1: C56.1 U13.8 | length 96.2
  Top Layer w15: C56.1@6755.91,3051.17 6764.59,3059.86 6846.66,3059.86 U13.8@6848,3061.2
NetC57_2: C57.2 R34.1 | length 80.3
  Top Layer w15: C57.2@6837,2903.52 R34.1@6917.32,2903.5
NetC62_1: C62.1 U12.9 | length 106.2
  Top Layer w20: U12.9@12629.92,1818.9 12710.36,1818.9 12727.5,1836.04 C62.1@12729,1836.04
NetC63_2: C63.2 U12.13 X4.1 | length 573.5
  Top Layer w15: U12.13@12629.92,2018.9 12737.52,2018.9 12823.63,2105 12940.81,2105 12949.59,2096.21 12949.59,2070.09 C63.2@12956.69,2062.99 12956.69,1964.57 12925.2,1933.07 X4.1@12889.76,1933.07
NetC64_2: C64.2 U12.14 X4.2 | length 662.4
  Top Layer w15: U12.14@12629.92,2068.9 12741.9,2068.9 12808,2135 12987.05,2135 13043.06,2078.99 13044.56,2078.99 13059.06,2064.49 C64.2@13059.06,2062.99 13059.06,1956.69 13082.68,1933.07 X4.2@13118.11,1933.07
NetC65_1: C65.1 U12.10 USB1.D+ | length 1569.9
  Top Layer w8: U12.10@12629.92,1868.9 12654.82,1868.9 12684,1898.07 12684,1917 12707,1940 12757.37,1940 12773,1924.37 12773,1856 12826,1803 12857.37,1803 12916.37,1744 13527.63,1744 13567,1783.37 13567,1904.63 13518.63,1953 13448.57,1953 13417.32,1984.25 USB1.D+@13381.89,1984.25 13267.47,1984.25 C65.1@13266.75,1983.53
NetC66_1: C66.1 U12.11 USB1.D- | length 1493.2
  Top Layer w8: U12.11@12629.92,1918.9 12633.17,1922.15 12666.52,1922.15 12700.37,1956 12764,1956 12789,1931 12789,1862.63 12832.63,1819 12864,1819 12923,1760 13521,1760 13551,1790 13551,1898 13512,1937 13448.81,1937 13417.32,1905.51 USB1.D-@13381.89,1905.51 13271.51,1905.51 C66.1@13267,1901
NetC121_1: C121.1 R100.2 R101.1 U31.6 | length 499.6
  Top Layer w20: U31.6@8981,3690.16 8981.16,3690 v1(9025,3690)
  Bottom Layer w20: v1(9025,3690) 8995,3720 8995,3930 C121.1@9044,3979 R101.1@9110.93,3979 R100.2@9177.86,3979
NetCF1_25: CF1.25 CF1.26 | length 1648.2
  Top Layer w8: CF1.26@12147.64,2609.65 12150.89,2612.9 12203.9,2612.9 12360,2769 12360,3014.63 12439,3093.63 12439,3432 v1(12470,3463) ; CF1.25@12148.64,3784.65 12443.65,3784.65 v1(12445,3786)
  Bottom Layer w8: v1(12445,3786) 12470,3761 v1(12470,3463)
NetD3_K: D3.K L3.2 U22.0 U22.3
NetD4_A: D4.A Q2.3
NetD5_A: D5.A L4.1 U31.1 U31.2
NetD8_K: D8.K R23.1 | length 137.3
  Bottom Layer w15: D8.K@5830.71,2543.31 5915.63,2458.39 5917.17,2458.39 5927.17,2448.39 R23.1@5927.17,2446.89
NetD9_A: D9.A R22.1 | length 127.4
  Bottom Layer w15: D9.A@5925.2,2543.31 5937.38,2531.12 5937.38,2514.62 5990,2462 5990,2456.89 R22.1@6000,2446.89
NetD9_K: D9.K D10.K SW1.3 | length 1606.3
  Bottom Layer w10: D9.K@5925.2,2685.04 5933.07,2692.91 5933.07,3170.84 5885.83,3218.09 5885.83,3340.83 6147,3602 6147,3726.06 6381.89,3960.94 SW1.3@6381.89,3968.5
  Bottom Layer w15: D9.K@5925.2,2685.04 D10.K@6019.68,2685.04
NetD10_A: D10.A Q2.1 R26.1 | length 3343.2
  Top Layer w10: v1(7215,3584) 7657,3584 7728,3655 7955,3655 7989,3689 7989,3871 8018,3900 8222,3900 8244.09,3922.09 Q2.1@8244.09,4019.69
  Bottom Layer w10: R26.1@6074.8,2444.88 6074.8,2488.19 D10.A@6019.68,2543.31 6034.37,2557.99 6123,2646.62 6123,2944.88 6248.03,3069.91 6248.03,3151.03 6646,3549 7180,3549 v1(7215,3584)
NetD11_A: D11.A R2.2 | length 308.6
  Bottom Layer w20: R2.2@9900,342 9900,340.5 9907.5,333 9909,333 9962,280 10134,280 D11.A@10168,314
NetL5_2: L5.2 U32.7
NetLED1_1: LED1.1 R136.2 | length 79.1
  Bottom Layer w10: R136.2@7857,4051 7858.27,4049.73 LED1.1@7858.27,3972.44
NetLED2_1: LED2.1 R137.2 | length 78.9
  Bottom Layer w10: R137.2@7621.33,4051 7621.33,3973.15 LED2.1@7622.05,3972.44
NetLED3_1: LED3.1 R138.2 | length 74.7
  Bottom Layer w10: R138.2@7385.67,4051 7385.83,4050.84 LED3.1@7385.83,3976.38
NetLED4_1: LED4.1 R139.2 | length 78.7
  Bottom Layer w10: LED4.1@7149.61,3972.44 7150,3972.83 R139.2@7150,4051
NetLED5_1: LED5.1 R130.1 | length 89.5
  Top Layer w10: LED5.1@5767.72,409.45 v1(5767.72,448.82)
  Bottom Layer w10: v1(5767.72,448.82) 5780.2,461.3 R130.1@5780.2,493.8
NetLED6_1: LED6.1 R131.1 | length 198.9
  Top Layer w10: LED6.1@5767.72,350.39 v1(5800.9,350.39)
  Bottom Layer w10: v1(5800.9,350.39) 5800.9,407.2 5854.67,460.96 R131.1@5854.67,493.8
NetQ1_B: Q1.B R3.2 | length 67.7
  Bottom Layer w25: R3.2@12570,1452 12571.67,1450.33 12634.63,1450.33 Q1.B@12636.29,1448.67
NetQ1_C: Q1.C SP1.2 | length 237.4
  Bottom Layer w25: Q1.C@12716.29,1486.67 12851.44,1486.67 SP1.2@12923.77,1559
NetQ3_4: Q3.4 R22.2 R23.2 R27.1 | length 257.7
  Top Layer w15: v1(5799,2350) 5799,2378.91 5803.16,2383.07 Q3.4@5811.02,2383.07
  Bottom Layer w15: v1(5799,2350) 5799.96,2350.96 5824.9,2350.96 5854.33,2380.39 R27.1@5854.33,2381.89 R23.2@5927.17,2381.89 R22.2@6000,2381.89
NetR15_2: R15.2 U40.45 | length 724.7
  Top Layer w8: v1(8201,2560) 8201.11,2560.11 8307.33,2560.11 U40.45@8307.43,2560.21 ; U40.45@8307.43,2560.11 8323.33,2560.11 U40.45@8323.43,2560.21
  Bottom Layer w12: v1(8201,2560) 8201,2438.92 8452,2187.92 8452,2108.39 8420.11,2076.5 R15.2@8418.61,2076.5
NetR16_2: R16.2 U40.46 | length 685.5
  Top Layer w8: v1(8181,2583) 8182,2582 8273.12,2582 8273.44,2581.68 8276.38,2581.68 8277.43,2580.63 8306.7,2580.63 U40.46@8307.43,2579.9
  Bottom Layer w8: v1(8181,2583) 8179,2581 8179,2435.46 8431,2183.46 8431,2147.94 R16.2@8418.61,2135.55
NetR24_1: R24.1 U14.12 | length 307.9
  Top Layer w12: R24.1@7246,2375 7277,2375 7299,2397 7336,2397 7427,2488 7427,2502.46 7457.54,2533 U14.12@7480,2533
NetR24_2: R24.2 U16.6 U16.7 | length 165.2
  Top Layer w12: U16.7@7068,2430.38 U16.6@7068,2380.38 7175.62,2380.38 R24.2@7181,2375
NetR25_1: R25.1 R124.1 U22.2 | length 360
  Top Layer w20: U22.2@6660.43,3931.14 6661.29,3932 v1(6754,3932)
  Bottom Layer w20: v1(6754,3932) 6883.59,3932 6924.59,3973 R124.1@6926.09,3973 6926.04,3973.04 R25.1@6926,4050 R25.1@6926,4050
NetR34_2: R34.2 U13.7 | length 188.4
  Top Layer w15: U13.7@6848,3111.2 6877,3111.2 6917.32,3070.87 R34.2@6917.32,2968.5
NetR35_1: R35.1 U13.10 | length 203.9
  Top Layer w15: R35.1@6992.13,2968.5 6992.13,3086.13 7015.86,3109.86 7066.66,3109.86 U13.10@7068,3111.2
NetR81_2: R81.2 U40.43 | length 753.1
  Top Layer w8: v1(8246,2514) 8249.25,2514 8256.09,2520.84 U40.43@8307.43,2520.84
  Bottom Layer w8: v1(8246,2514) 8246,2442 8492,2196 8492,2030.28 8420.11,1958.39 R81.2@8418.61,1958.39
NetR82_2: R82.2 U40.44 | length 748.4
  Top Layer w8: v1(8225,2537) 8227.3,2539.3 8235.45,2539.3 8236.69,2540.53 U40.44@8307.43,2540.53 ; U40.44@8307.43,2539.8 8322.7,2539.8 U40.44@8323.43,2540.53
  Bottom Layer w8: v1(8225,2537) 8223.7,2535.7 8223.7,2528.02 8223,2527.31 8223,2442.37 8474,2191.37 8474,2071.33 8420.11,2017.44 R82.2@8418.61,2017.44
NetR103_1: R103.1 U30.4 U30.11 | length 461.3
  Bottom Layer w8: U30.11@13374.02,2393.7 13399.23,2393.7 13405.69,2400.17 13405.69,2406.69 13423,2424 13509,2424 ; R103.1@13508,2636 13508,2425 13509,2424 ; U30.4@13594.02,2393.7 13565.02,2393.7 13534.72,2424 13509,2424
NetR107_1: R107.1 U2.13 U30.12 | length 894.7
  Top Layer w8: v1(13477,2851) v1(13477,2907)
  Bottom Layer w8: U2.13@13194.49,2907.09 13194.54,2907.05 v1(13477,2907) v1(13477,2907) ; U30.12@13374.02,2443.7 13403.02,2443.7 13442,2482.69 R107.1@13442,2636 13442,2637.5 13474.5,2670 13532,2670 13544,2682 13544,2784 v1(13477,2851)
NetR108_2: R108.2 R109.2 U28.1 | length 147.5
  Bottom Layer w8: U28.1@12976.38,3257.09 12972.47,3257.09 12966,3263.56 R109.2@12966,3331 R108.2@13033,3331
NetR130_2: R130.2 U32.1 | length 140.4
  Top Layer w10: U32.1@5807,688 U32.1@5807,688 5807.04,626.03 v1(5807.09,625.98)
  Bottom Layer w10: R130.2@5780.2,558.8 5780.2,599.09 v1(5807.09,625.98)
NetR131_2: R131.2 U32.3 | length 150.9
  Top Layer w10: v1(5905.51,622.05) 5906.26,622.79 5906.26,687.26 U32.3@5907,688
  Bottom Layer w10: R131.2@5854.67,558.8 5854.67,560.3 5903.6,609.24 5903.6,620.13 v1(5905.51,622.05)
NetR132_2: R132.2 U32.4 | length 140.7
  Top Layer w10: v1(5956.69,622.05) 5956.85,622.2 5956.85,687.85 U32.4@5957,688
  Bottom Layer w10: R132.2@5929.13,558.8 5929.13,594.49 v1(5956.69,622.05)
NetR133_2: R133.2 U32.2 | length 811.5
  Top Layer w10: v1(5767.4,1131.55) 5748.03,1112.18 5748.03,622.05 5775.59,594.49 5842.52,594.49 5857,608.97 U32.2@5857,688
  Bottom Layer w10: v1(5767.4,1131.55) 5852.69,1131.55 R133.2@5855,1133.86
NetR134_1: R134.1 U32.6 | length 116.6
  Top Layer w10: U32.6@5907,908 5909.68,910.68 5909.68,949.05 v1(5929.13,968.5)
  Bottom Layer w10: R134.1@5927,922.43 5929.13,924.56 v1(5929.13,968.5)
NetU2_2: U2.2 U21.1 | length 1432.5
  Top Layer w8: v1(12757,2654) 13197,2654 13327,2784 v1(13327,3211)
  Bottom Layer w8: U21.1@12751.5,2543.7 12757,2549.2 v1(12757,2654) ; v1(13327,3211) 13328.95,3209.05 13592.54,3209.05 U2.2@13594.49,3207.09
NetU2_4: U2.4 U21.4 | length 1676.7
  Top Layer w8: v1(12682,2448) 12684,2450 13062,2450 13085,2473 13365,2473 13581,2689 13581,2941.11 13544.11,2978 13513,2978 13492,2999 13492,3108 v1(13493,3109)
  Bottom Layer w8: v1(12682,2448) 12684.3,2445.7 12684.3,2431.9 12722.5,2393.7 U21.4@12751.5,2393.7 ; v1(13493,3109) 13493.95,3108.05 13593.54,3108.05 U2.4@13594.49,3107.09
NetU2_6: U2.6 U21.10 | length 1633
  Top Layer w8: v1(12590,2517) 12591.94,2518.94 13046.53,2518.94 13052.46,2513 13128.11,2513 13133.11,2518 13387.37,2518 13565,2695.63 13565,2925 13535,2955 v1(13535,2956)
  Bottom Layer w8: U21.10@12531.5,2343.7 12560.5,2343.7 12589,2372.2 12589,2516 v1(12590,2517) ; v1(13535,2956) 13535,2975 13561.3,3001.3 13562.44,3001.3 13568.24,3007.09 U2.6@13594.49,3007.09
NetU9_2: U9.2 U9.3 U18.4 U20.1 | length 1543.7
  Top Layer w8: v1(12687,1747) 12822,1747 12866,1703 v1(13111,1703)
  Layer 2 w8: v1(13111,1703) 13111,1810 13134.04,1833.04 13134.04,1912.96 13116,1931 v1(13116,2007) 13153,2044 13153,2413 v1(13121,2445)
  Bottom Layer w8: v1(12687,1747) 12687,1822.31 12722.5,1857.8 U18.4@12751.5,1857.8 ; v1(13116,2007) 13116.4,2007.4 13172.35,2007.4 U20.1@13172.76,2007.8 ; v1(13121,2445) 13121.65,2444.35 13172.11,2444.35 U9.3@13172.76,2443.7 U9.2@13172.76,2493.7
NetU9_4: U9.4 U25.12 | length 1934
  Top Layer w8: v1(11586,2445) 11710,2569 11961,2569 12062,2468 12274,2468 12297,2491 12470,2491 12561,2400 13019.11,2400 13029.11,2410 13098.89,2410 13109.89,2421 v1(13233,2421)
  Bottom Layer w8: U25.12@11520.16,2443.7 11520.81,2444.35 11585.35,2444.35 v1(11586,2445) ; U9.4@13172.76,2393.7 13203.73,2393.7 13231.03,2421 v1(13233,2421)
NetU9_10: U9.10 U9.11 U9.12 | length 100
  Bottom Layer w8: U9.10@12952.76,2343.7 U9.11@12952.76,2393.7 U9.12@12952.76,2443.7
NetU9_13: U9.13 U20.15 | length 646.4
  Bottom Layer w8: U20.15@12952.76,1957.8 12955,1960.04 12996.04,1960.04 13013,1977 13013,2386 13033,2406 13033,2447.61 12992.6,2488.01 12991.23,2488.01 12985.54,2493.7 U9.13@12952.76,2493.7
NetU14_14: U14.14 U16.1 U16.2 | length 866.1
  Top Layer w12: U16.1@6848,2480.38 U16.2@6848,2430.38 6872.75,2430.38 6878.3,2424.83 6878.3,2418.7 7050,2247 7311,2247 7393,2329 7393,2376 7448.09,2431.09 7478.09,2431.09 U14.14@7480,2433
NetU17_13: U17.13 U19.7 | length 365.8
  Bottom Layer w8: U19.7@11740.16,1707.8 11864.78,1707.8 12014.78,1857.8 U17.13@12043.78,1857.8
NetU17_15: U17.15 U19.9 | length 686.6
  Bottom Layer w8: U19.9@11520.16,1657.8 11552.95,1657.8 11567.14,1672 11642,1672 11701,1731 11854,1731 11984,1861 11984,1927.02 12014.78,1957.8 U17.15@12043.78,1957.8
NetU18_13: U18.13 U19.10 | length 1262.5
  Bottom Layer w8: U19.10@11520.16,1707.8 11491.16,1707.8 11468.16,1684.8 11468.16,1648.28 11485.43,1631 11632,1631 11681.8,1680.8 12321.71,1680.8 12498.71,1857.8 U18.13@12531.5,1857.8
NetU29_2: U29.2 U30.1 | length 809.5
  Layer 2 w8: v1(13561,2573) 13561,2452.75 13479.03,2370.77 13479.03,2248.34 13642,2085.37 v1(13642,1983)
  Bottom Layer w8: v1(13561,2573) 13563.3,2570.7 13563.3,2550.17 13569.76,2543.7 U30.1@13594.02,2543.7 ; U29.2@13594.02,1957.8 13620.91,1957.8 13620.91,1958.8 13642,1979.89 v1(13642,1983)
NetU29_5: U29.5 U30.5 | length 736
  Layer 2 w8: v1(13538,2346) 13564,2320 13564,2235 13696,2103 13696,1853 v1(13651,1808)
  Bottom Layer w8: v1(13538,2346) 13539.15,2344.85 13592.87,2344.85 U30.5@13594.02,2343.7 ; U29.5@13594.11,1807.9 13650.9,1807.9 v1(13651,1808)
NetU29_7: U29.7 U30.3 | length 950.5
  Layer 2 w8: v1(13651,1708) 13728,1785 13728,2167 13658,2237 v1(13658,2467)
  Bottom Layer w8: U30.3@13594.02,2443.7 13623.02,2443.7 13644.02,2464.7 13655.7,2464.7 v1(13658,2467) ; U29.7@13594.11,1707.9 13650.9,1707.9 v1(13651,1708)
NetU29_10: U29.10 U30.9 | length 788.9
  Bottom Layer w8: U29.10@13374.02,1707.8 13345.02,1707.8 13319,1733.82 13319,1773 13329,1783 13414,1783 13427,1796 13427,1849 13445,1867 13445,2277 13428.3,2293.7 U30.9@13374.02,2293.7
OPL3SW#: U19.1 U40.3 | length 4404.4
  Top Layer w8: U40.3@8215.9,2671.43 8215.9,2710.86 8253.73,2748.69 8351.15,2748.69 8409,2690.84 8409,2510.63 8445,2474.63 8445,2336.37 8568.37,2213 9138.25,2213 9151.25,2200 9453,2200 9553,2100 10231.49,2100 10445.19,2313.7 11161.16,2313.7 11209.16,2361.7 11408.67,2361.7 11427.37,2343 11512.25,2343 11591.25,2264 v1(11680,2264)
  Bottom Layer w8: v1(11680,2264) 11680,2168 11740.16,2107.84 U19.1@11740.16,2007.8
OSC: J1.4 J6.48 J7.48 U1.117 U10.24 X2.3 | length 9280.3
  Top Layer w8: v1(10684,695) v1@10684.1,695.1 ; U1.117@10776.67,695.1 U1.117@10776.77,695.2
  Top Layer w10: U10.24@7938,2927 v1(7938,2983) ; v1(7938,3227) 7939,3228 8207,3228 8557,2878 8590.13,2878 8593.4,2881.27 8626.53,2881.27 8629.57,2878.23 8680.83,2878.23 8681.1,2877.95 8733.62,2877.95 v1(8751,2895.33) ; 9238.54,2892 9360.95,2892 9375,2877.95 J7.48@9527.56,2877.95 ; v1(9967,821) 10558,821 v1(10684,695) ; v1@10684.1,695.1 U1.117@10776.67,695.1
  Top Layer w12: v1@9962,3867 9962.53,3867.53 9976.59,3867.53 9979.06,3870 10890,3870 11075,4055 11075,4285.63 11114.17,4324.8 J1.4@11114.17,4330.71
  Bottom Layer w8: X2.3@10628,695.64 X2.3@10628.64,695
  Bottom Layer w10: v1(7938,2983) v1(7938,3227) ; v1(9228,2895.47) 9254.72,2895.47 9257.52,2892.66 9281.53,2892.66 9281.86,2893 9299.74,2893 9376,2816.74 9376,2370.04 9524.53,2221.51 9717.84,2221.51 9870,2069.35 9870,1579.04 9915.5,1533.54 9915.5,872.5 v1(9967,821) ; X2.3@10628.64,695 v1(10684,695)
  Bottom Layer w12: v1(8751,2895.33) 8749.47,2893.8 8742.26,2893.8 8739.65,2891.2 8667.78,2891.2 8658.85,2882.27 8607.06,2882.27 8605.82,2881.03 8590.97,2881.03 8586.94,2877 8561.38,2877 8485,2953.38 8485,3173.62 8624.38,3313 8878.46,3313 8965.46,3400 9276.08,3400 9647.08,3771 9796.94,3771 9840.94,3815 9911,3815 v1(9962,3866) ; v1@8751.13,2895.33 8890.99,2895.33 8909.32,2877 9132.47,2877 9150.94,2895.47 v1(9228,2895.47)
PWG: C9.2 R1.2 U1.113 | length 690.3
  Top Layer w8: v1(10375.94,474.06) 10375.94,561.94 10430.46,616.46 U1.113@10776.77,616.46
  Bottom Layer w8: v1(10375.94,474.06) 10375.94,473.06 10421.5,427.5 10421.5,422 10436.5,407 10522,407 C9.2@10523,408
R: C53.2 C55.1 P1.2 VR2.2 | length 1742.9
  Top Layer w15: P1.2@5940.94,3244.09 5940.94,3074.8 6027.56,2988.19 6322.83,2988.19 6385.83,2925.2 VR2.2@6385.83,2811.02 6596.02,2811.02 6624,2839 7091,2839 7114,2862 7114,2963 7119.51,2968.51 ; C55.1@7066.93,2968.5 7119.51,2968.51 ; C53.2@7161.42,2968.52 7119.51,2968.51
RASJ0: U1.84 U3.14 | length 2934
  Top Layer w8: v1(10197,509) 10197,507.26 10270.38,433.88 10270.38,402.77 10278.8,394.35 10278.8,355.06 U1.84@10279.53,354.33 ; U3.14@11780,248 11780,550 11755,575 11755,751 11805,801 v1@11805,1010
  Bottom Layer w8: v1(10197,509) 10197,689.25 10426.75,919 10956.35,919 11082.35,1045 11772,1045 v1(11807,1010)
RASJ1: U1.83 U4.14 | length 2380.4
  Top Layer w8: v1(10171,534) 10173.3,531.7 10173.3,523.23 10173.74,522.79 10173.74,501.14 10254.38,420.51 10254.38,396.14 10259.11,391.41 10259.11,355.06 U1.83@10259.84,354.33 ; U4.14@11780,840 11780,1014.11 11806.94,1041.06 v1(11807.06,1041.06)
  Bottom Layer w8: v1(10171,534) 10171,685.88 10420.12,935 10949.73,935 11075.73,1061 11787.11,1061 v1(11807.06,1041.06)
RASJ2: U1.82 U5.14 | length 4120.4
  Top Layer w8: v1(10151.74,513.67) 10153.23,512.19 10153.23,491.67 10238.38,406.52 10238.38,389.51 10239.43,388.46 10239.43,355.06 U1.82@10240.16,354.33 ; U5.14@12914,248 12914,530 12890,554 12890,751 12939,800 v1@12939,972
  Bottom Layer w8: v1(10151.74,513.67) 10149.45,515.97 10149.45,524.44 10149,524.89 10149,686.51 10413.49,951 10943.1,951 11069.1,1077 11802.23,1077 11871.23,1008 12863,1008 12899,972 v1(12940,972)
RASJ3: U1.80 U6.14 | length 3514.2
  Top Layer w8: v1(10128,493) 10200.06,420.94 10200.06,355.06 U1.80@10200.79,354.33 ; U6.14@12914,840 v1@12914,995
  Bottom Layer w8: v1(10128,493) 10128,688.14 10406.86,967 10932,967 11058,1093 11810,1093 11876,1027 12883,1027 v1(12915,995)
RED25: LED4.2 U40.13 | length 2076.6
  Top Layer w8: U40.13@7985.84,2620 7986.2,2619.63 8040.63,2619.63 v1(8041,2620)
  Bottom Layer w8: LED4.2@7082.68,3972.44 7082.68,3970.47 7094.43,3958.72 7096.39,3958.72 7170.12,3885 7508,3885 7652,3741 7652,3325.13 7769,3208.13 7769,2768 7917,2620 v1(8041,2620)
REFSH#: J1.26 J6.54 J7.54 R54.1 U1.163 | length 8436.3
  Top Layer w8: v1(8576.89,2949) 8580.13,2949 8592.13,2937.01 J6.54@8681.1,2937.01 ; v1(9272,2961.8) 9372.21,2961.8 9397,2937.01 J7.54@9527.56,2937.01 ; v1(9875,3749) 11018.88,3749 11074.88,3693 11593.37,3693 11775.37,3875 11959.37,3875 12019,3934.63 12019,4286.12 11980.32,4324.8 J1.26@11980.32,4330.71 ; v1(9985,1385) 9987,1385 10031,1341 10366.67,1341 10554.39,1528.72 10554.39,1566.83 U1.163@10555.12,1567.56
  Bottom Layer w8: v1(9985,1385) 9987,1387 9987,1543.04 9921,1609.04 9921,2090.47 9738.96,2272.51 9545.66,2272.51 9427,2391.17 9427,2837.86 9303.06,2961.8 v1(9272,2961.8) 8717.43,2961.8 8704.63,2949 v1(8576.89,2949) 8573.64,2949 8568.64,2954 8566.04,2954 8539,2981.04 8539,3151.26 8646.74,3259 8900.82,3259 8987.82,3346 9298.45,3346 9669.45,3717 9830,3717 9860.94,3747.94 9873.94,3747.94 v1(9875,3749) 9909.5,3749 10002,3656.5 R54.1@10002,3655
RESET: J1.60 J6.64 J7.64 R44.1 U1.162 U12.2 | length 11168.2
  Top Layer w8: v1(8605,3051) 8608.25,3051 8623.25,3036 8680.54,3036 J6.64@8681.1,3035.43 ; v1(9228,3072) 9386.44,3072 9423,3035.43 J7.64@9527.56,3035.43 ; v1(10097,1319) 10367.29,1319 10574.07,1525.78 10574.07,1566.83 U1.162@10574.8,1567.56 10574.8,1615.08 10573,1616.89 10573,1742.26 10791.74,1961 v1(11190,1961) ; v1(12415,2760) 12376,2799 12376,3008 12455,3087 12455,3415 12501,3461 12501,3551.19 12905.81,3956 13070.86,3956 13357,4242.14 13357,4282 13318.9,4320.1 J1.60@13318.9,4330.71 ; v1(12460,1517) 12497,1517 12545.1,1468.9 U12.2@12629.92,1468.9
  Bottom Layer w8: v1(8605,3051) 8668,3051 8727,3110 8826,3110 8846,3090 9210,3090 v1(9228,3072) 9306,3072 9507,2871 9507,2424.3 9578.3,2353 9800.25,2353 10001,2152.25 10001,1642.18 10094,1549.18 10094,1477 10103,1468 10103,1398.12 10097,1392.12 v1(10097,1319) ; v1(11190,1961) 11190,1675 11321,1544 11976,1544 12015,1583 12235,1583 12300,1518 12460,1518 12461,1517 12488,1517 12555,1584 12634.25,1584 12674,1623.75 12674,1699 12705.8,1730.8 12834.8,1730.8 12862,1758 12862,1795 12901,1834 13004,1834 13029,1859 13029,2376.88 13049,2396.88 13049,2454.24 13018,2485.24 13018,2612 13047.28,2641.28 13047.28,2720.1 13021.37,2746 12842,2746 12828,2760 v1(12415,2760) 12415,2704 R44.1@12416,2703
